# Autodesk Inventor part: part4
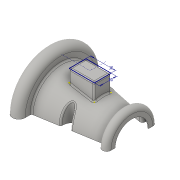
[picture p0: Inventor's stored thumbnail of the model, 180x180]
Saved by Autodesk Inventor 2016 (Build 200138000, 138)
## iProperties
Created: 2015-05
Part Number: part4
Material: Generic
Document SubType Name: Modeling
Designer: Sandeep
Density: 1 g/cm^3
Appearance: Default
Author: Sandeep
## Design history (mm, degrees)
sketch "Sketch1"
  geometry: L1 (-36.486, 0)-(29.175, 0) reference; L2 (-50, 30)-(-50, 42.5); L3 (-35, 42.5)-(-35, 35); L4 (-35, 35)-(40, 22.5); L5 (40, 22.5)-(40, 25); L6 (50, 25)-(50, 20); A1 r 7.5 centre (-42.5, 42.5) between (-35, 42.5) and (-50, 42.5); A2 r 5 centre (45, 25) between (50, 25) and (40, 25); 1 further point
  constraints: 12 end point, 4 point on circle, 4 tangent, 3 parallel, 2 centre point, 2 horizontal, 1 point on line, 1 vertical
  dimensions: "d1" = 50 distance from line of point (0, 0) L2; "d2" = 100 distance between parallel lines of L2 L6; "d3" = 5 radius of A2; "d4" = 7.5 radius of A1; "d5" = 85 diameter of L2.end L1; "d6" = 60 diameter of L2.start L1; "d7" = 70 diameter of L3.end L1; "d9" = 50 diameter of L6.start L1; "d10" = 45 diameter of L4.end L1; "d11" = 40 diameter of L6.end L1
feature "RevolutionSrf1" sketch "Sketch1" dims angle "d12" = 180 deg
sketch "Sketch2" dims "d14" = 10, "d15" = 5
  geometry: L1 (-35, 35)-(40, 22.5) reference; L2 (50, -25)-(50, 25) reference; 2 further points; 1 other entity
  constraints: 1 point on line, 2 other
  dimensions: "d13" = 50 distance from line of L2 point (0, 29.167)
extrude_surface "ExtrusionSrf1" sketch "Sketch2" dims "d16" = 30, "d17" = 0
mirror "Mirror1"
feature "Trim1"
feature "Trim2"
feature "Trim3"
feature "Trim4"
workplane "Work Plane1"
sketch "Sketch3"
  geometry: L1 (-15, 10)-(15, 10); L2 (15, 10)-(15, -10); L3 (15, -10)-(-15, -10); L4 (-15, -10)-(-15, 10); L5 (0, 19.961)-(0, 0); L6 (0, 0)-(-34.336, 0)
  constraints: 12 end point, 2 horizontal, 2 parallel, 1 perpendicular, 1 vertical, 2 other
  dimensions: "d19" = 30 distance between parallel lines of L2 L4; "d20" = 20 distance of L1.end L2.end
split "Split1"
delete_face "Delete Face1"
sketch "3D Sketch1"
  geometry: L1 through (0, 0) direction (1, 0) reference; L2 through (0, 0) direction (-1, 0) reference; 4 other entities
  constraints: 6 horizontal
feature "Stitch Surface1"
fillet "Fillet1" dims "d25" = 2
fillet "Fillet2" dims "d26" = 2
feature "Stitch Surface3"
thicken "Thicken1" dims "d28" = 1
fillet "Fillet4" dims "d29" = 2
body "Solid1"
body "Srf1"
body "Srf2"
body "Srf3"
node "Edges1"
body "Srf4"
body "Srf5"
body "Srf6"
body "Srf8"
extrude_surface "ExtrusionSrf2"
feature "LoftSrf1" dims "d21" = 0, "d22" = 90 deg, "d23" = 0, "d24" = 90 deg
patch "Boundary Patch1"
other parameters: "d18" = 45
